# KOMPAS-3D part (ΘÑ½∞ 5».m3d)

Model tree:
1. Эскиз:1
2. Операция выдавливания:1
     Расстояние 1 = 2
3. Эскиз:2
4. Операция выдавливания:2
     Расстояние 1 = 5
5. Эскиз:3
6. Операция выдавливания:3
     Расстояние 1 = 2
7. Эскиз:4
8. Операция выдавливания:4
     Расстояние 1 = 78
9. Эскиз:5
10. Операция выдавливания:5
     Расстояние 1 = 2
11. Эскиз:6
12. Операция выдавливания:6
     Расстояние 1 = 4.5
13. Эскиз:7
14. Операция выдавливания:7
     Расстояние 1 = 2
15. Скругление:1
     Радиус = 1
16. Скругление:2
     Радиус = 1
17. Эскиз:8
18. Вырезать элемент выдавливания:1
     Расстояние 1 = 10; Угол 1 = 35
19. Эскиз:9
20. Вырезать элемент выдавливания:2
     Расстояние 1 = 10; Угол 1 = 35
21. Эскиз:10
22. Вырезать элемент выдавливания:3
     Расстояние 2 = 22; Расстояние 1 = 22; Угол 1 = 35
23. Эскиз:11
24. Вырезать элемент выдавливания:4
     Расстояние 2 = 2; Расстояние 1 = 2
25. Эскиз:12
26. Вырезать элемент выдавливания:5
     Расстояние 2 = 2; Расстояние 1 = 2; Угол 1 = 35
27. Эскиз:13
28. Вырезать элемент выдавливания:6
     Расстояние 2 = 2; Расстояние 1 = 122
29. Эскиз:14
30. Вырезать элемент выдавливания:7
     Расстояние 2 = 100; Расстояние 1 = 60
